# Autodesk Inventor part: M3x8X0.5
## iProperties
IsCustomPart: 1
Created: 2009-02
Part Number: M3x8X0.5
Material: 강, 연강
Description: 6각머리 태핑 나사
Document SubType Name: Modeling
Standard: KS B 1003
Designer: SeoGD™[esajin.kr]
Standards Organization: KS
Language: ko-KR
Size Designation: M 3 x 8
Categories: <MemberInstance><Categories><Category DisplayName="조임쇠" InternalName="e4da775c-781d-43d5-af7c-5136215cf5a6" Mnemonic="FSTN"><Category DisplayName="볼트" InternalN
Density: 1 g/cm^3
Author: SeoGD™[esajin.kr]
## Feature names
1. Fillet2
